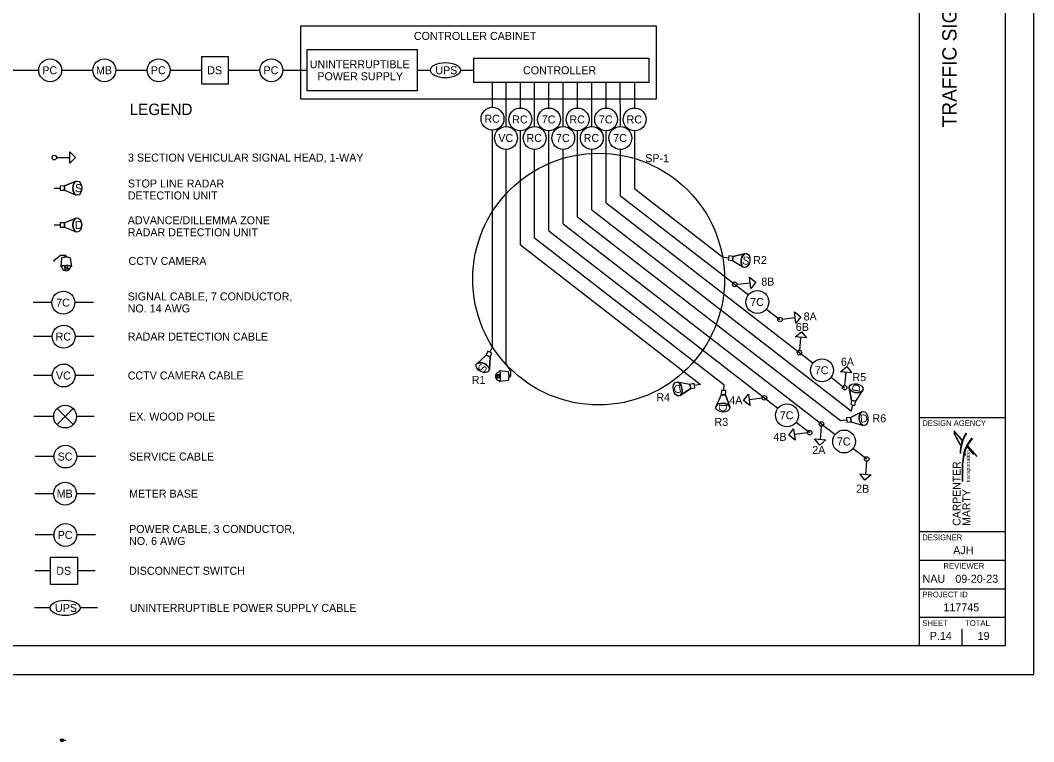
# Model space of a CAD drawing. Extents: x 0 to 680, y -24 to 440.
# Drawn here: x 325.4 to 680, y -23.6 to 229 of the extents above; entities that cross this region are included whole.
import ezdxf

# ---------------------------------------------------------------- set-up
doc = ezdxf.new("R2010")
doc.units = 0
for name, color, linetype in [('SG_P_Detection', 7, 'Continuous'), ('SG_P_Heads', 7, 'Continuous'), ('SG_P_Text', 7, 'Continuous'), ('SH_Border', 7, 'Continuous'), ('SH_Cut_Line', 7, 'Continuous'), ('SH_Data', 7, 'Continuous'), ('SH_Text', 7, 'Continuous'), ('ST_Text', 7, 'Continuous')]:
    doc.layers.add(name, color=color, linetype=linetype)

msp = doc.modelspace()

# ---------------------------------------------------------------- linework, layer by layer
at = {"layer": 'SG_P_Detection'}
for p, q in [((337.28, 170.26), (339.4, 170.26)), ((340.9, 171.02), (345.02, 172.67)), ((345.02, 172.67), (340.9, 171.02)), ((340.9, 171.02), (340.9, 169.52)), ((340.9, 169.52), (345.02, 167.86)), ((340.9, 169.52), (345.02, 167.86)), ((340.88, 158.13), (344.99, 159.79)), ((344.99, 159.79), (340.88, 158.13)), ((337.26, 157.38), (339.38, 157.38)), ((340.88, 158.13), (340.88, 156.63)), ((340.88, 156.63), (344.99, 154.98)), ((340.88, 156.63), (344.99, 154.98)), ((339.91, 145.73), (339.6, 142.79)), ((341.39, 146.73), (341.4, 146.36)), ((342.91, 145.8), (343.35, 142.87)), ((571.15, 146.19), (573.24, 145.86)), ((574.84, 146.36), (574.61, 144.88)), ((574.84, 146.36), (579.17, 147.35)), ((579.17, 147.35), (574.84, 146.36)), ((337.26, 144.58), (337.25, 145.33)), ((340.94, 143.11), (340.98, 141.42)), ((341.99, 143.13), (342.03, 141.44)), ((574.61, 144.88), (578.41, 142.6)), ((574.61, 144.88), (578.41, 142.6)), ((490.64, 114.76), (489.74, 112.84)), ((488.43, 111.8), (485.18, 108.78)), ((488.43, 111.8), (485.18, 108.78)), ((489.79, 111.17), (488.43, 111.8)), ((489.79, 111.17), (489.54, 106.74)), ((489.54, 106.74), (489.79, 111.17)), ((495.02, 108.58), (495.77, 108.59)), ((493.48, 104.94), (491.78, 104.93)), ((493.48, 103.89), (491.78, 103.89)), ((496.12, 105.91), (493.19, 106.29)), ((496.13, 102.92), (493.19, 102.54)), ((497.09, 104.42), (496.71, 104.42)), ((559.68, 101.57), (555.32, 102.38)), ((559.68, 101.57), (555.32, 102.38)), ((559.98, 100.1), (556.27, 97.67)), ((556.27, 97.67), (559.98, 100.1)), ((559.98, 100.1), (559.68, 101.57)), ((559.68, 101.57), (559.98, 100.1)), ((563.38, 101.55), (561.3, 101.13)), ((571.6, 101.51), (571.5, 99.39)), ((616.27, 95.94), (615.45, 100.3)), ((615.45, 100.3), (616.27, 95.94)), ((617.74, 95.65), (620.17, 99.36)), ((617.74, 95.65), (620.17, 99.36)), ((570.69, 97.92), (568.85, 93.89)), ((570.69, 97.92), (568.85, 93.89)), ((572.19, 97.86), (570.69, 97.92)), ((570.69, 97.92), (572.19, 97.86)), ((572.19, 97.86), (573.65, 93.67)), ((573.65, 93.67), (572.19, 97.86)), ((616.27, 95.94), (617.74, 95.65)), ((617.74, 95.65), (616.27, 95.94)), ((616.3, 92.25), (616.71, 94.33)), ((612.4, 88.94), (614.51, 89.12)), ((615.94, 90), (619.9, 92)), ((619.9, 92), (615.94, 90)), ((615.94, 90), (616.07, 88.5)), ((616.07, 88.5), (615.94, 90)), ((616.07, 88.5), (620.31, 87.2)), ((616.07, 88.5), (620.31, 87.2))]:
    msp.add_line(p, q, dxfattribs=at)
for points in [[(339.4, 171.01), (339.4, 169.51), (340.9, 169.52), (340.9, 171.02)], [(339.38, 158.13), (339.38, 156.63), (340.88, 156.63), (340.88, 158.13)], [(573.36, 146.6), (573.13, 145.12), (574.61, 144.88), (574.84, 146.36)], [(490.42, 112.52), (489.06, 113.16), (488.43, 111.8), (489.79, 111.17)], [(561.45, 100.4), (561.15, 101.87), (559.68, 101.57), (559.98, 100.1)], [(572.25, 99.36), (570.75, 99.42), (570.69, 97.92), (572.19, 97.86)], [(615.98, 94.47), (617.45, 94.18), (617.74, 95.65), (616.27, 95.94)], [(614.45, 89.87), (614.58, 88.38), (616.07, 88.5), (615.94, 90)]]:
    msp.add_lwpolyline(points, close=True, dxfattribs=at)
for points in [[(339.4, 171.01), (339.4, 169.51), (340.9, 169.52), (340.9, 171.02), (339.4, 171.01)], [(339.38, 158.13), (339.38, 156.63), (340.88, 156.63), (340.88, 158.13), (339.38, 158.13)], [(341.39, 146.73), (339.52, 146.69), (337.26, 144.95)], [(341.03, 146.05), (341.02, 146.35), (341.77, 146.37), (341.78, 146.07)], [(573.36, 146.6), (573.13, 145.12), (574.61, 144.88), (574.84, 146.36), (573.36, 146.6)], [(490.42, 112.52), (489.06, 113.16), (488.43, 111.8), (489.79, 111.17), (490.42, 112.52)], [(497.09, 104.42), (497.09, 106.29), (495.39, 108.58)], [(496.41, 104.79), (496.71, 104.79), (496.72, 104.04), (496.42, 104.04)], [(559.98, 100.1), (561.45, 100.4), (561.15, 101.87), (559.68, 101.57)], [(572.19, 97.86), (572.25, 99.36), (570.75, 99.42), (570.69, 97.92)], [(616.27, 95.94), (615.98, 94.47), (617.45, 94.18), (617.74, 95.65)], [(615.94, 90), (614.45, 89.87), (614.58, 88.38), (616.07, 88.5)]]:
    msp.add_lwpolyline(points, dxfattribs=at)
for centre, major_axis, ratio in [((345.39, 170.26), (0, -2.48), 0.621318), ((345.37, 157.38), (0, -2.48), 0.621318), ((579.16, 144.91), (-0.39, -2.45), 0.621318), ((341.49, 142.25), (0.023, 0.409), 0.999249), ((487.2, 107.42), (-2.24, 1.05), 0.621318), ((492.61, 104.41), (0.408, -0.032), 0.999249), ((555.43, 99.95), (-0.49, 2.43), 0.621318), ((617.88, 100.2), (2.43, -0.48), 0.621318), ((571.23, 93.41), (-2.48, 0.11), 0.621318), ((620.48, 89.63), (0.21, -2.47), 0.621318)]:
    msp.add_ellipse(centre, major_axis=major_axis, ratio=ratio, dxfattribs=at)
for centre, major_axis, ratio, start_param, end_param in [((345.39, 170.26), (0, -2.48), 0.621318, 3.386213, 6.038231), ((345.37, 157.38), (0, -2.48), 0.621318, 3.386213, 6.038231), ((341.41, 145.77), (1.5, 0.03), 0.200149, 6.283161, 9.424753), ((579.16, 144.91), (-0.39, -2.45), 0.621318, 3.386213, 6.038231), ((341.47, 142.83), (1.87, 0.04), 0.160119, 5.62984, 10.078084), ((341.47, 142.83), (0.09, 1.5), 0.999249, 1.527523, 4.912851), ((487.2, 107.42), (-2.24, 1.05), 0.621318, 3.386213, 6.038231), ((493.19, 104.41), (0, -1.87), 0.160119, 5.62984, 10.078084), ((493.19, 104.41), (1.5, -0.12), 0.999249, 1.527523, 4.912851), ((496.12, 104.42), (0, -1.5), 0.200149, 6.283161, 9.424753), ((555.43, 99.95), (-0.49, 2.43), 0.621318, 3.386213, 6.038231), ((617.88, 100.2), (2.43, -0.48), 0.621318, 3.386213, 6.038231), ((571.23, 93.41), (-2.48, 0.11), 0.621318, 3.386213, 6.038231), ((620.48, 89.63), (0.21, -2.47), 0.621318, 3.386213, 6.038231)]:
    msp.add_ellipse(centre, major_axis=major_axis, ratio=ratio, start_param=start_param, end_param=end_param, dxfattribs=at)
at = {"layer": 'SG_P_Heads'}
for p, q in [((338.13, 180.96), (342.73, 180.96)), ((576.22, 136.64), (580.79, 137.13)), ((592.01, 124.38), (596.57, 124.95)), ((598.12, 113.44), (598.55, 118.02)), ((613.93, 101.2), (614.37, 105.78)), ((584.98, 96.75), (580.42, 96.17)), ((605.69, 86.89), (605.3, 82.31)), ((600.82, 84.56), (596.26, 83.97)), ((621.5, 74.64), (621.1, 70.06))]:
    msp.add_line(p, q, dxfattribs=at)
for points in [[(342.73, 182.96), (344.73, 180.96), (342.73, 178.96)], [(580.58, 139.11), (582.78, 137.34), (581, 135.14)], [(596.32, 126.93), (598.56, 125.2), (596.82, 122.96)], [(596.57, 118.21), (598.75, 120.01), (600.55, 117.83)], [(612.38, 105.97), (614.56, 107.77), (616.36, 105.59)], [(580.67, 94.18), (578.43, 95.91), (580.16, 98.15)], [(596.51, 81.99), (594.28, 83.72), (596.01, 85.96)], [(607.29, 82.14), (605.12, 80.32), (603.3, 82.48)], [(623.1, 69.89), (620.93, 68.07), (619.11, 70.23)]]:
    msp.add_lwpolyline(points, close=True, dxfattribs=at)
for centre in [(337.33, 180.96), (575.42, 136.55), (591.22, 124.28), (598.04, 112.65), (613.86, 100.41), (585.77, 96.85), (601.61, 84.66), (605.76, 87.69), (621.57, 75.44)]:
    msp.add_circle(centre, 0.8, dxfattribs=at)
at = {"layer": 'SG_P_Text'}
for p, q in [((336.5, 130.18), (329.96, 130.18)), ((351.04, 130.18), (344.5, 130.18)), ((336.63, 118.28), (330.09, 118.28)), ((351.18, 118.28), (344.63, 118.28)), ((336.63, 104.67), (330.09, 104.67)), ((351.18, 104.67), (344.63, 104.67)), ((338.29, 93.11), (343.94, 87.46)), ((338.29, 87.46), (343.94, 93.11)), ((337.12, 90.29), (330.2, 90.29)), ((351.28, 90.29), (345.12, 90.29)), ((337.23, 76.29), (330.69, 76.29)), ((351.78, 76.29), (345.23, 76.29)), ((337.1, 63.29), (330.56, 63.29)), ((351.64, 63.29), (345.1, 63.29)), ((337.23, 48.83), (330.69, 48.83)), ((351.78, 48.83), (345.23, 48.83)), ((336.02, 36.29), (330.55, 36.29)), ((351.63, 36.29), (345.5, 36.29)), ((335.89, 23.29), (330.42, 23.29)), ((352.5, 23.29), (346.36, 23.29))]:
    msp.add_line(p, q, dxfattribs=at)
for points in [[(388.83, 206.8), (398.3, 206.8), (398.3, 216.28), (388.83, 216.28)], [(336.02, 41.03), (345.5, 41.03), (345.5, 31.55), (336.02, 31.55)]]:
    msp.add_lwpolyline(points, close=True, dxfattribs=at)
for centre in [(335.88, 211.54), (354.86, 211.54), (373.85, 211.54), (413.29, 211.54), (340.5, 130.18), (340.63, 118.28), (340.63, 104.67), (341.12, 90.29), (341.23, 76.29), (341.1, 63.29), (341.23, 48.83)]:
    msp.add_circle(centre, 4, dxfattribs=at)
at = {"layer": 'SH_Border'}
for p, q in [((640, 10), (640, 430)), ((640, 90), (670, 90)), ((640, 50), (670, 50)), ((640, 40), (670, 40)), ((640, 30), (670, 30)), ((640, 20), (670, 20))]:
    msp.add_line(p, q, dxfattribs=at)
msp.add_lwpolyline([(30, 430), (670, 430), (670, 10), (30, 10)], close=True, dxfattribs=at)
at = {"layer": 'SH_Cut_Line'}
msp.add_lwpolyline([(0, 0), (680, 0), (680, 440), (0, 440)], close=True, dxfattribs=at)
at = {"layer": 'SH_Data'}
for p, q in [((655, 70), (655, 70)), ((655, 10), (655, 16)), ((647.5, 13.5), (647.5, 13.5))]:
    msp.add_line(p, q, dxfattribs=at)
msp.add_lwpolyline([(425.79, 204.3), (425.79, 218.78), (464.31, 218.78), (464.31, 204.3)], close=True, dxfattribs=at)
at = {"layer": 'SH_Text'}
for p, q in [((484.04, 215.79), (484.04, 207.29)), ((484.04, 215.79), (545.39, 215.79)), ((545.39, 215.79), (545.39, 207.29)), ((545.39, 207.29), (484.04, 207.29)), ((490.64, 198.56), (490.64, 207.29)), ((495.39, 191.82), (495.39, 207.29)), ((500.39, 198.32), (500.39, 207.29)), ((505.39, 191.82), (505.39, 207.29)), ((510.39, 198.32), (510.39, 207.29)), ((515.39, 191.82), (515.36, 207.29)), ((520.39, 198.32), (520.39, 207.29)), ((525.39, 191.82), (525.36, 207.29)), ((530.39, 198.32), (530.39, 207.29)), ((535.39, 191.82), (535.36, 207.29)), ((540.39, 198.32), (540.39, 207.29)), ((490.64, 114.76), (490.64, 190.56)), ((500.39, 150.36), (500.39, 190.32)), ((510.39, 155.26), (510.39, 190.32)), ((520.39, 160.17), (520.39, 190.32)), ((530.39, 165.07), (530.39, 190.32)), ((540.39, 170.02), (540.39, 190.32)), ((495.39, 108.58), (495.39, 183.82)), ((505.39, 152.81), (505.39, 183.82)), ((515.39, 157.72), (515.39, 183.82)), ((525.39, 162.62), (525.39, 183.82)), ((535.39, 167.57), (535.39, 183.82)), ((535.39, 167.57), (580.17, 132.88)), ((540.39, 170.02), (571.15, 146.19)), ((530.39, 165.07), (602.78, 108.97)), ((520.39, 160.17), (612.36, 88.9)), ((525.39, 162.62), (616.26, 92.2)), ((515.39, 157.72), (610.5, 84.01)), ((505.39, 152.81), (571.6, 101.51)), ((510.39, 155.26), (590.51, 93.18)), ((500.39, 150.36), (563.38, 101.55)), ((586.47, 127.95), (591.22, 124.28)), ((609.11, 104.08), (613.79, 100.33)), ((596.87, 88.33), (601.61, 84.66)), ((654.41, 80.33), (652.03, 84.64)), ((616.82, 79.11), (621.57, 75.44)), ((659.03, 77.05), (656.68, 79.83)), ((656.78, 80.03), (660.12, 76.32)), ((656.22, 76.81), (655.79, 77.6)), ((656.4, 76.67), (655.83, 77.72)), ((655.1, 67.55), (655.1, 74.08)), ((655.23, 67.55), (655.23, 74.08)), ((339.47, -23.04), (340.52, -23.04)), ((340, -23.04), (341.35, -23.04))]:
    msp.add_line(p, q, dxfattribs=at)
msp.add_lwpolyline([(423.54, 227.06), (547.88, 227.06), (547.88, 201.46), (423.54, 201.46)], close=True, dxfattribs=at)
for points in [[(654.92, 82.09), (652.02, 85.32)], [(652.02, 85.32), (654.88, 81.96)], [(654.41, 80.33), (652.03, 84.64)], [(652.03, 84.63), (654.39, 80.22)]]:
    msp.add_lwpolyline(points, dxfattribs=at)
for centre, radius in [((490.64, 194.56), 4), ((500.39, 194.32), 4), ((510.39, 194.32), 4), ((520.41, 194.32), 4), ((530.39, 194.32), 4), ((540.39, 194.32), 4), ((495.39, 187.82), 4), ((505.39, 187.82), 4), ((515.39, 187.82), 4), ((525.39, 187.82), 4), ((535.39, 187.82), 4), ((527.79, 138.42), 44.05), ((583.32, 130.41), 4), ((605.93, 106.5), 4), ((593.67, 90.73), 4), ((613.66, 81.56), 4), ((340, -23.04), 0.521)]:
    msp.add_circle(centre, radius, dxfattribs=at)
for centre, radius, start, end in [((668.65, 77.2), 14.41, 149.5704, 179.5529), ((667.46, 77.23), 13.09, 147.1423, 179.6525), ((668.51, 74.08), 13.41, 139.2898, 180.0106), ((668.67, 73.76), 13.43, 138.5126, 178.6075)]:
    msp.add_arc(centre, radius, start, end, dxfattribs=at)
for centre in [(474.17, 211.54), (341.13, 23.29)]:
    msp.add_ellipse(centre, major_axis=(5.24, 0), ratio=0.509539, dxfattribs=at)
at = {"layer": 'ST_Text'}
for p, q in [((320.9, 211.54), (331.88, 211.54)), ((339.88, 211.54), (350.86, 211.54)), ((358.86, 211.54), (369.85, 211.54)), ((377.85, 211.54), (388.83, 211.54)), ((398.3, 211.54), (409.29, 211.54)), ((417.29, 211.54), (425.79, 211.54)), ((464.31, 211.54), (468.93, 211.54)), ((479.41, 211.54), (484.04, 211.54))]:
    msp.add_line(p, q, dxfattribs=at)

# ---------------------------------------------------------------- texts
at = {"layer": 'SG_P_Detection'}
for s, rotation, p in [('S', 0.0227, (344.58, 168.86)), ('D', 0.0227, (344.54, 155.98)), ('S', 350.9716, (577.85, 143.7)), ('S', 244.9247, (486.4, 109.01)), ('D', 191.3902, (556.39, 101.57)), ('D', 78.7649, (619.01, 98.69)), ('D', 267.4188, (569.89, 94.73)), ('D', 4.8983, (619.34, 88.13))]:
    msp.add_text(s, height=2.8, rotation=rotation, dxfattribs=at).set_placement(p)
at = {"layer": 'SG_P_Text'}
for s, p in [('PC', (333.14, 210.14)), ('MB', (351.93, 210.14)), ('PC', (371.11, 210.14)), ('DS', (390.84, 210.14)), ('PC', (410.55, 210.14)), ('SP-1', (544.08, 179.34)), ('MB', (338.17, 61.89)), ('PC', (338.5, 47.43))]:
    msp.add_text(s, height=2.8, rotation=360, dxfattribs=at).set_placement(p)
for s, p in [('7C', (337.98, 128.78)), ('RC', (337.79, 116.88)), ('VC', (337.9, 103.27)), ('SC', (338.5, 74.89)), ('DS', (338.03, 34.89))]:
    msp.add_text(s, height=2.8, dxfattribs=at).set_placement(p)
at = {"layer": 'SH_Data'}
msp.add_text('TRAFFIC SIGNAL DETAILS - MIA-US40-1.637', height=5, rotation=90, dxfattribs=at).set_placement((653, 191.54))
for s, height, p in [('DESIGN AGENCY', 2, (641, 87)), ('DESIGNER', 2, (641, 47)), ('AJH', 2.8, (651.81, 42.1)), ('REVIEWER', 2, (648.44, 37)), ('NAU', 2.8, (641.1, 32.1)), ('09-20-23', 2.8, (652.58, 32.1)), ('PROJECT ID', 2, (641, 27)), ('117745', 2.8, (648.42, 22.1)), ('SHEET', 2, (641, 17)), ('TOTAL', 2, (656, 17)), ('P.14', 2.8, (643.63, 12.1)), ('19', 2.8, (660.38, 12.1))]:
    msp.add_text(s, height=height, dxfattribs=at).set_placement(p)
at = {"layer": 'SH_Text'}
for s, height, rotation, p in [('CONTROLLER CABINET', 2.8, 360, (463.13, 222.16)), ('UNINTERRUPTIBLE', 2.8, 360, (426.7, 212.24)), ('CONTROLLER', 2.8, 360, (501.33, 210.14)), ('POWER SUPPLY', 2.8, 360, (429.37, 208.04)), ('RC', 2.8, 360, (487.8, 193.16)), ('RC', 2.8, 360, (497.55, 192.92)), ('7C', 2.8, 360, (507.88, 192.92)), ('RC', 2.8, 360, (517.56, 192.92)), ('7C', 2.8, 360, (527.87, 192.92)), ('RC', 2.8, 360, (537.54, 192.92)), ('VC', 2.8, 360, (492.66, 186.42)), ('RC', 2.8, 360, (502.55, 186.42)), ('7C', 2.8, 360, (512.88, 186.42)), ('RC', 2.8, 360, (522.55, 186.42)), ('7C', 2.8, 360, (532.88, 186.42)), ('7C', 2.8, 360, (580.8, 129.01)), ('7C', 2.8, 360, (603.41, 105.1)), ('R1', 2.8, 360, (483.39, 101.73)), ('R5', 2.8, 360, (616.57, 102.7)), ('R4', 2.8, 360, (547.96, 95.66)), ('R3', 2.8, 360, (568.32, 87.01)), ('7C', 2.8, 360, (591.15, 89.33)), ('7C', 2.8, 360, (611.14, 80.16)), ('transportation', 1.3298, 90, (657.7, 67.28)), ('CARPENTER ', 2.735, 90, (654.38, 52.04)), ('METER BASE', 2.8, 360, (363.5, 61.89)), ('MARTY', 2.735, 90, (657.81, 52.04)), ('POWER CABLE, 3 CONDUCTOR,', 2.8, 360, (363.5, 49.53)), ('NO. 6 AWG', 2.8, 360, (363.5, 45.33))]:
    msp.add_text(s, height=height, rotation=rotation, dxfattribs=at).set_placement(p)
for s, height, p in [('UPS', 2.8, (470.63, 210.14)), ('LEGEND', 4, (363.68, 195.85)), ('3 SECTION VEHICULAR SIGNAL HEAD, 1-WAY', 2.8, (363.11, 179.56)), ('STOP LINE RADAR', 2.8, (363.08, 170.49)), ('DETECTION UNIT', 2.8, (363.08, 166.29)), ('ADVANCE/DILLEMMA ZONE', 2.8, (363.05, 157.61)), ('RADAR DETECTION UNIT', 2.8, (363.05, 153.41)), ('CCTV CAMERA', 2.8, (363.3, 143.38)), ('R2', 2.8, (581.85, 143.7)), ('8B', 2.8, (584.67, 136.15)), ('SIGNAL CABLE, 7 CONDUCTOR, ', 2.8, (363, 130.95)), ('NO. 14 AWG', 2.8, (363, 126.75)), ('8A', 2.8, (599.5, 123.94)), ('6B', 2.8, (596.76, 120.26)), ('RADAR DETECTION CABLE', 2.8, (363.03, 116.88)), ('6A', 2.8, (612.54, 108.08)), ('CCTV CAMERA CABLE', 2.8, (363.03, 103.27)), ('4A', 2.8, (573.47, 94.6)), ('EX. WOOD POLE', 2.8, (363.51, 88.89)), ('R6', 2.8, (623.59, 88.3)), ('4B', 2.8, (588.93, 81.79)), ('2A', 2.8, (602.52, 77.19)), ('SERVICE CABLE', 2.8, (363.5, 74.89)), ('2B', 2.8, (617.88, 63.63)), ('DISCONNECT SWITCH', 2.8, (363.48, 34.89)), ('UPS', 2.8, (337.58, 21.89)), ('UNINTERRUPTIBLE POWER SUPPLY CABLE', 2.8, (363.78, 21.89)), ('$CD010', 0.0656, (339.83, -23.24)), ('2', 0.0656, (339.97, -22.91)), ('Drawing - Copy-1', 0.0656, (340.65, -22.91)), ('1:1', 0.0656, (340.65, -23.24))]:
    msp.add_text(s, height=height, dxfattribs=at).set_placement(p)

doc.saveas('drawing.dxf')
